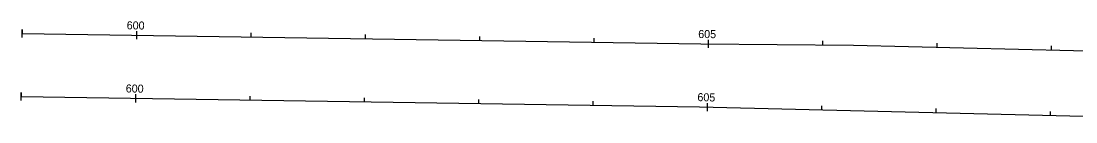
# Model space of a CAD drawing. Extents: x 596008 to 607538, y 326212 to 405053.
# Drawn here: x 602077 to 602999, y 349932 to 350019 of the extents above; entities that cross this region are included whole.
import ezdxf

# ---------------------------------------------------------------- set-up
doc = ezdxf.new("R2010")
doc.units = 0
doc.layers.add('P_ALI', color=7, linetype='Continuous')
doc.layers.add('P_ALI_200_Sta', color=7, linetype='Continuous')

msp = doc.modelspace()

# ---------------------------------------------------------------- linework, layer by layer
at = {"layer": 'P_ALI'}
for points in [[(602077.76, 350008.55), (602671.33, 349999.57)], [(602671.33, 349999.57), (602805.06, 349998.35)], [(602805.06, 349998.35), (603189.84, 349989.09)], [(602076.92, 349953.56), (602670.26, 349944.58)], [(602670.26, 349944.58), (603210.1, 349931.59)]]:
    msp.add_lwpolyline(points, dxfattribs=at)
at = {"layer": 'P_ALI_200_Sta'}
for points in [[(602077.7, 350005.05), (602077.76, 350008.55)], [(602077.76, 350008.55), (602077.81, 350012.05)], [(602077.76, 350008.55), (602077.76, 350008.55)], [(602078.14, 350008.55), (602078.19, 350012.04)], [(602178.07, 350003.53), (602178.13, 350007.03)], [(602178.13, 350007.03), (602178.18, 350010.53)], [(602178.13, 350007.03), (602178.13, 350007.03)], [(602278.11, 350005.52), (602278.17, 350009.02)], [(602378.1, 350004.01), (602378.16, 350007.51)], [(602478.09, 350002.49), (602478.14, 350005.99)], [(602578.08, 350000.98), (602578.13, 350004.48)], [(602678.04, 349996.01), (602678.07, 349999.51)], [(602678.07, 349999.51), (602678.1, 350003.01)], [(602678.07, 349999.51), (602678.07, 349999.51)], [(602778.07, 349998.6), (602778.1, 350002.1)], [(602878.04, 349996.6), (602878.13, 350000.09)], [(602978.01, 349994.19), (602978.1, 349997.69)], [(602076.86, 349950.06), (602076.92, 349953.56)], [(602076.92, 349953.56), (602076.97, 349957.06)], [(602076.92, 349953.56), (602076.92, 349953.56)], [(602077.31, 349953.55), (602077.36, 349957.05)], [(602177.24, 349948.54), (602177.29, 349952.04)], [(602177.29, 349952.04), (602177.35, 349955.54)], [(602177.29, 349952.04), (602177.29, 349952.04)], [(602277.28, 349950.53), (602277.34, 349954.03)], [(602377.27, 349949.01), (602377.32, 349952.51)], [(602477.26, 349947.5), (602477.31, 349951)], [(602577.25, 349945.99), (602577.3, 349949.49)], [(602677.15, 349940.91), (602677.24, 349944.41)], [(602677.24, 349944.41), (602677.32, 349947.91)], [(602677.24, 349944.41), (602677.24, 349944.41)], [(602777.21, 349942.01), (602777.29, 349945.5)], [(602877.18, 349939.6), (602877.26, 349943.1)], [(602977.15, 349937.19), (602977.23, 349940.69)]]:
    msp.add_lwpolyline(points, dxfattribs=at)

# ---------------------------------------------------------------- texts
for s, height, rotation, p in [('599', 0.0000000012, 359.13314, (602077.83, 350013.55)), ('600', 7, 359.13314, (602169.2, 350012.17)), ('605', 7, 359.47811, (602669.12, 350004.59)), ('599', 0.0000000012, 359.13314, (602076.99, 349958.56)), ('600', 7, 359.13314, (602168.37, 349957.17)), ('605', 7, 358.6212, (602668.36, 349949.63))]:
    msp.add_text(s, height=height, rotation=rotation, dxfattribs=at).set_placement(p)

doc.saveas('drawing.dxf')
